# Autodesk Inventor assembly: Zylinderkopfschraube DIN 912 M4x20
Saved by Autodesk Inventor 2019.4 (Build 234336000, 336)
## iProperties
Created: 2021-06
Part Number: Zylinderkopfschraube DIN 912 M4x20
Document SubType Name: Assembly
Designer: Administrator
Title: Zylinderkopfschraube DIN 912 M4x20 v2
Author: Administrator
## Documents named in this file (2)
- c:\worker\convert-fusion-r04\tmp\job-1\39\output\files\e1e84fd7-b652-4e3d-a1c7-f0a54bbc30a7\Zylinderkopfschraube DIN 912 M4x20 v2_2.iam
- c:\worker\convert-fusion-r04\tmp\job-1\39\output\files\e1e84fd7-b652-4e3d-a1c7-f0a54bbc30a7\HI_WUERTH 00824  20 cylinder head screw DIN 912 M4x20 8.8 BLK.ipt
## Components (1 placed, 1 different names)
1. HI_WUERTH 00824  20 cylinder head screw DIN 912 M4x20 8.8 BLK:1
